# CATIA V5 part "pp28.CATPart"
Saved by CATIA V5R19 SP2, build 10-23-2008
Part number: pp28
Bounding box of the stored display mesh (mm): x -15 to -10, y 49.85 to 102.25, z 24.619 to 52.25
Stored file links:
  C:\Users\Welcome\Documents\thinkm2\pp28.CATPart
  C:\Users\Welcome\Documents\thinkm2\Brasmeca.CATProduct
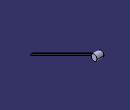
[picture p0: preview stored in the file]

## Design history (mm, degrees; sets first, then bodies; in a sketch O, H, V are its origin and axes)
AxisSystem1: origin (0, 0, 0), X (1, 0, 0), Y (0, 1, 0), Z (0, 0, 1)
Set1
  Plane1: linked copy from another document
  Line1: linked copy from another document
  Plane2: linked copy from another document
Body1 (main body)
  Sketch1 on Plane1, origin (-15, 0, 0), H (0, 1, 0), V (0, 0, 1)
    circle A1 centre (100, 50) radius 2.25
    reference projected point E1 (100, 50) from Line1
    radius A1 = 2.25
    distance A1 E1 = 2.25
  Pad1: profile Sketch1, direction (1, 0, 0), length 5
  Sketch2 on Plane2, origin (0, 50, 25), H (1, 0, 0), V (0, -0.4472, 0.8944)
    line L1 (-14.9757, 0.3357) -> (-13.3097, 0.3357)
    line L2 (-13.3097, 0.3357) -> (-13.3097, -0.4263)
    line L3 (-13.3097, -0.4263) -> (-14.9757, -0.4263)
    line L4 (-14.9757, -0.4263) -> (-14.9757, 0.3357)
  Pad2: profile Sketch2, direction (0, 0.8944, 0.4472), length 58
